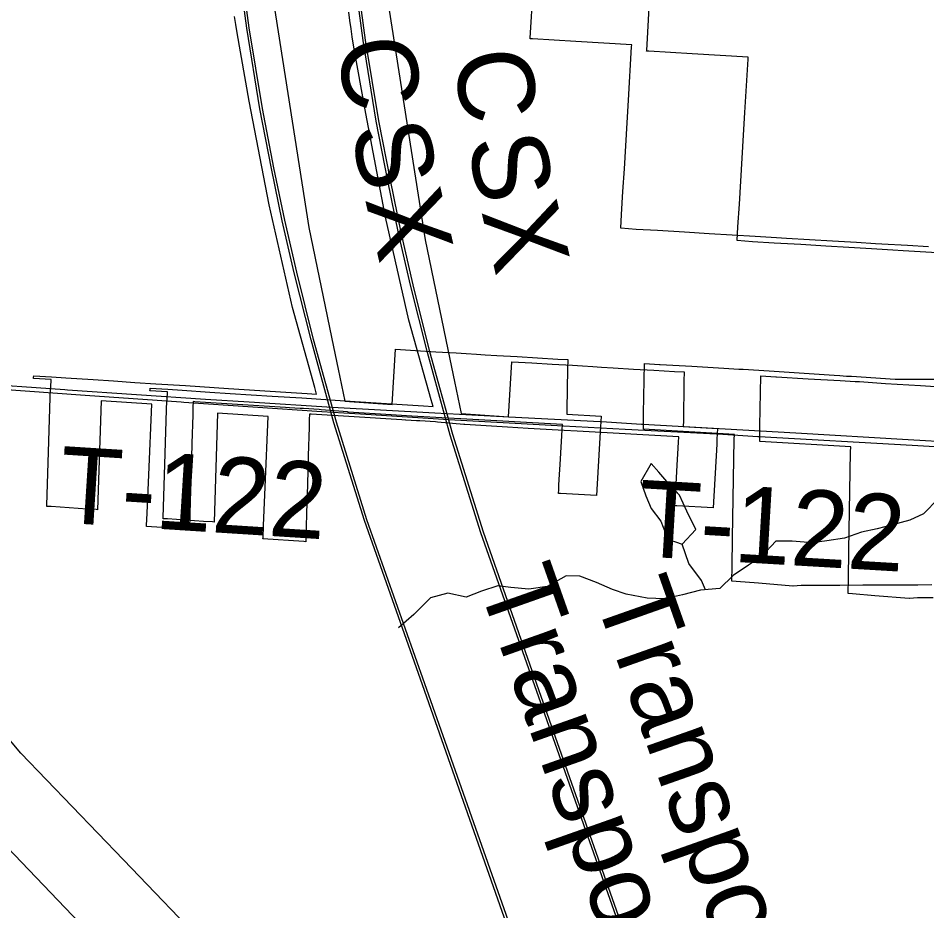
# Model space of a CAD drawing. Extents: x -38.2 to 41.9, y -4 to 24.9.
# Drawn here: x 6.275 to 6.95, y 18.764 to 19.427 of the extents above; entities that cross this region are included whole.
import ezdxf

# ---------------------------------------------------------------- set-up
doc = ezdxf.new("R2010")
doc.units = 0
for name, color, linetype in [('Default', 7, 'Continuous'), ('GM_X_City_Street', 7, 'Continuous'), ('GM_X_County_Road', 7, 'Continuous'), ('GM_X_Minor_Lake', 7, 'Continuous'), ('GM_X_Minor_River', 7, 'Continuous'), ('GM_X_Rail_Line', 7, 'Continuous'), ('GM_X_Rail_Line_Text', 7, 'Continuous'), ('GM_X_State_Location', 7, 'Continuous'), ('GM_X_Township_Road', 7, 'Continuous'), ('GM_X_Township_Road_Text', 7, 'Continuous')]:
    doc.layers.add(name, color=color, linetype=linetype)

msp = doc.modelspace()

# ---------------------------------------------------------------- linework, layer by layer
at = {"layer": 'Default'}
for points in [[(6.4559, 19.496), (6.49098, 19.27124), (6.50937, 19.18266), (6.51282, 19.16603), (6.51773, 19.14237), (6.55298, 19.1398), (6.55534, 19.18085), (6.57023, 19.17996), (6.58536, 19.17906), (6.60048, 19.17816), (6.60787, 19.17771), (6.61561, 19.17725), (6.62191, 19.17688), (6.63073, 19.17633), (6.64585, 19.1754), (6.66098, 19.17446), (6.6761, 19.17352), (6.68337, 19.17321), (6.68326, 19.16635), (6.68279, 19.13613), (6.68275, 19.13341), (6.68274, 19.13269), (6.70813, 19.13127), (6.70785, 19.12728), (6.70778, 19.12329), (6.70756, 19.11955), (6.70487, 19.0722), (6.67794, 19.07373), (6.67651, 19.07381), (6.67667, 19.07664), (6.67688, 19.08026), (6.67796, 19.09933), (6.67798, 19.09962), (6.6792, 19.12115), (6.67941, 19.12494), (6.60396, 19.12922), (6.59437, 19.12976), (6.56752, 19.13129), (6.55218, 19.13216), (6.52035, 19.13427), (6.51963, 19.13431), (6.50014, 19.13596), (6.49861, 19.13606), (6.48705, 19.13683), (6.48643, 19.13687), (6.48454, 19.13699), (6.47666, 19.13749), (6.47641, 19.13751), (6.47373, 19.13767), (6.43814, 19.13992), (6.40628, 19.14192), (6.40501, 19.142), (6.40489, 19.13798), (6.40472, 19.13231), (6.4041, 19.11091), (6.40347, 19.08961), (6.40285, 19.06832), (6.40224, 19.04762), (6.40222, 19.04712), (6.40095, 19.0472), (6.37048, 19.04918), (6.3705, 19.04991), (6.37079, 19.05925), (6.37205, 19.0877), (6.37438, 19.14014), (6.33664, 19.14266), (6.3341, 19.06172), (6.33307, 19.06179), (6.3264, 19.06224), (6.29948, 19.06405), (6.29637, 19.06417), (6.29639, 19.0649), (6.29785, 19.11275), (6.29885, 19.14519), (6.29892, 19.14709), (6.2993, 19.15276), (6.29966, 19.15844), (6.2865, 19.15929), (6.28654, 19.16001), (6.2866, 19.16118), (6.29978, 19.16033), (6.31041, 19.15964), (6.33089, 19.15832), (6.34598, 19.15734), (6.36167, 19.15633), (6.37736, 19.15531), (6.39934, 19.15389), (6.43122, 19.15183), (6.47396, 19.14907), (6.48986, 19.14804), (6.49681, 19.14759), (6.49545, 19.15243), (6.47884, 19.2118), (6.46147, 19.28819), (6.44678, 19.36513), (6.43774, 19.41587), (6.43681, 19.42202), (6.4359, 19.42817)], [(6.95154, 19.25696), (6.93589, 19.25787), (6.91687, 19.25898), (6.91211, 19.25926), (6.89801, 19.2601), (6.88011, 19.26118), (6.86306, 19.2622), (6.84602, 19.26323), (6.83844, 19.26368), (6.82271, 19.26463), (6.80564, 19.26566), (6.78857, 19.26668), (6.77015, 19.26779), (6.75017, 19.26899), (6.73414, 19.26995), (6.7228, 19.27093), (6.7234, 19.28094), (6.72442, 19.29796), (6.72544, 19.31497), (6.72645, 19.33199), (6.72747, 19.349), (6.72849, 19.36602), (6.73085, 19.40555), (6.73094, 19.40705), (6.68938, 19.40953), (6.67328, 19.4105), (6.65721, 19.41146), (6.65553, 19.41156), (6.65556, 19.41206), (6.65762, 19.44846)], [(6.95401, 19.00585), (6.94344, 19.00575), (6.93696, 19.00572), (6.93371, 19.00571), (6.92075, 19.00565), (6.91723, 19.00564), (6.90274, 19.00557), (6.88557, 19.00549), (6.87807, 19.00545), (6.86836, 19.0054), (6.85679, 19.00535), (6.85085, 19.00504), (6.85061, 19.00504), (6.82512, 19.00707), (6.80847, 19.00839), (6.80524, 19.00865), (6.80524, 19.00882), (6.80543, 19.01935), (6.80581, 19.04075), (6.80712, 19.1139), (6.80718, 19.11769), (6.73963, 19.12157), (6.73963, 19.12557), (6.73968, 19.1295), (6.73975, 19.13324), (6.74035, 19.17024), (6.75153, 19.1696), (6.75205, 19.16957), (6.77556, 19.16822), (6.79943, 19.16686), (6.81052, 19.16622), (6.81361, 19.16602), (6.833, 19.16476), (6.85908, 19.16307), (6.88129, 19.16162), (6.88543, 19.16136), (6.8905, 19.16103), (6.8942, 19.16079), (6.92671, 19.15867), (6.9422, 19.15865), (6.95656, 19.15863)]]:
    msp.add_lwpolyline(points, dxfattribs=at)
at = {"layer": 'GM_X_County_Road'}
for points in [[(6.54238, 19.48681), (6.57745, 19.26205), (6.59584, 19.17347), (6.5993, 19.15684), (6.60421, 19.13318), (6.63946, 19.13061), (6.64182, 19.17166), (6.65671, 19.17077), (6.67184, 19.16987), (6.68696, 19.16897), (6.69435, 19.16853), (6.70209, 19.16806), (6.70839, 19.16769), (6.71721, 19.16714), (6.73233, 19.16621), (6.74745, 19.16527), (6.76258, 19.16433), (6.76985, 19.16402), (6.76974, 19.15716), (6.76927, 19.12694), (6.76923, 19.12422), (6.76922, 19.1235), (6.79461, 19.12208), (6.79433, 19.11809), (6.79425, 19.1141), (6.79404, 19.11036), (6.79135, 19.06301), (6.76442, 19.06454), (6.76299, 19.06462), (6.76315, 19.06745), (6.76335, 19.07107), (6.76444, 19.09014), (6.76445, 19.09043), (6.76568, 19.11197), (6.76589, 19.11575), (6.69043, 19.12003), (6.68085, 19.12057), (6.654, 19.1221), (6.63865, 19.12297), (6.60683, 19.12508), (6.60611, 19.12512), (6.58662, 19.12677), (6.58508, 19.12688), (6.57353, 19.12765), (6.57291, 19.12768), (6.57102, 19.1278), (6.56314, 19.1283), (6.56288, 19.12832), (6.56021, 19.12849), (6.52462, 19.13073), (6.49275, 19.13273), (6.49148, 19.13281), (6.49137, 19.12879), (6.4912, 19.12312), (6.49057, 19.10172), (6.48995, 19.08042), (6.48932, 19.05913), (6.48872, 19.03843), (6.4887, 19.03793), (6.48742, 19.03801), (6.45696, 19.03999), (6.45698, 19.04072), (6.45726, 19.05006), (6.45853, 19.07851), (6.46085, 19.13095), (6.42312, 19.13347), (6.42058, 19.05253), (6.41954, 19.0526), (6.41288, 19.05305), (6.38596, 19.05486), (6.38284, 19.05498), (6.38287, 19.05571), (6.38433, 19.10356), (6.38533, 19.136), (6.38539, 19.1379), (6.38577, 19.14357), (6.38613, 19.14925), (6.37298, 19.1501), (6.37302, 19.15082), (6.37308, 19.15199), (6.38626, 19.15114), (6.39689, 19.15045), (6.41737, 19.14913), (6.43246, 19.14815), (6.44815, 19.14714), (6.46384, 19.14612), (6.48582, 19.1447), (6.51769, 19.14264), (6.56044, 19.13988), (6.57633, 19.13885), (6.58328, 19.1384), (6.58193, 19.14324), (6.56532, 19.20262), (6.54795, 19.279), (6.53326, 19.35594), (6.52422, 19.40668), (6.52329, 19.41283), (6.52238, 19.41898), (6.52148, 19.42513), (6.52062, 19.43123)], [(6.33156, 18.74361), (6.26678, 18.81099), (6.19068, 18.89012), (6.16568, 18.91927), (6.14879, 18.94351), (6.1397, 18.95874), (6.13142, 18.97442), (6.12397, 18.99051), (6.11949, 19.00145), (6.11538, 19.01254), (6.06671, 19.16827), (6.06312, 19.17932), (6.04638, 19.23325), (6.0322, 19.28484), (6.02363, 19.32547), (6.01909, 19.3528), (6.01409, 19.39407), (6.01194, 19.42186), (6.01053, 19.4664)], [(6.96659, 19.25199), (6.94954, 19.25302), (6.9325, 19.25404), (6.92492, 19.2545), (6.90918, 19.25544), (6.89212, 19.25647), (6.87505, 19.25749), (6.85663, 19.2586), (6.83665, 19.2598), (6.82062, 19.26076), (6.80928, 19.26174), (6.80988, 19.27176), (6.8109, 19.28877), (6.81191, 19.30578), (6.81293, 19.3228), (6.81395, 19.33981), (6.81497, 19.35683), (6.81733, 19.39636), (6.81742, 19.39786), (6.77585, 19.40034), (6.75976, 19.40131), (6.74369, 19.40227), (6.74201, 19.40237), (6.74204, 19.40287), (6.7441, 19.43927)], [(6.95483, 18.99621), (6.94327, 18.99616), (6.93733, 18.99585), (6.93708, 18.99585), (6.9116, 18.99788), (6.89494, 18.9992), (6.89172, 18.99946), (6.89172, 18.99963), (6.89191, 19.01016), (6.89229, 19.03156), (6.89359, 19.10471), (6.89366, 19.1085), (6.82611, 19.11238), (6.82611, 19.11638), (6.82615, 19.12031), (6.82622, 19.12405), (6.82683, 19.16105), (6.83801, 19.16041), (6.83853, 19.16038), (6.86203, 19.15903), (6.8859, 19.15767), (6.897, 19.15703), (6.90009, 19.15683), (6.91947, 19.15557), (6.94556, 19.15388), (6.96776, 19.15244)]]:
    msp.add_lwpolyline(points, dxfattribs=at)
at = {"layer": 'GM_X_Minor_Lake'}
for points in [[(6.75099, 19.08955), (6.74527, 19.09601), (6.7377, 19.08275), (6.74149, 19.07213), (6.74528, 19.06265), (6.75247, 19.05317), (6.75778, 19.0399), (6.76838, 19.03611)], [(6.76838, 19.03611), (6.77859, 19.0471), (6.77177, 19.06075), (6.76647, 19.0725), (6.757, 19.08274), (6.75099, 19.08955)]]:
    msp.add_lwpolyline(points, dxfattribs=at)
at = {"layer": 'GM_X_Minor_River'}
for points in [[(6.95873, 19.07015), (6.94776, 19.05878), (6.93754, 19.05385), (6.92468, 19.05045), (6.91332, 19.04742), (6.90159, 19.04515), (6.8891, 19.04061), (6.87586, 19.03872), (6.86488, 19.0372), (6.85012, 19.03835), (6.83801, 19.03835), (6.82742, 19.02698), (6.81758, 19.02054), (6.80623, 19.01297), (6.7964, 19.00311), (6.78201, 19.00198), (6.76877, 18.99858), (6.75515, 18.99555), (6.74228, 18.99593), (6.72676, 18.99897), (6.71654, 19.00239), (6.7048, 19.0077), (6.69231, 19.01226), (6.68209, 19.01264), (6.66809, 19.00469), (6.65447, 19.0028), (6.64122, 19.00394), (6.63138, 19.00508), (6.61927, 19.0013), (6.60792, 18.99675), (6.59429, 18.99979), (6.58143, 18.99638), (6.56894, 18.98388), (6.55759, 18.97402)], [(6.78566, 19.00227), (6.78277, 19.00918), (6.7733, 19.0217), (6.76838, 19.03611)]]:
    msp.add_lwpolyline(points, dxfattribs=at)
at = {"layer": 'GM_X_Rail_Line'}
for points in [[(6.82378, 18.22738), (6.69158, 18.60188), (6.65557, 18.70415), (6.57538, 18.93166), (6.53239, 19.05367), (6.50963, 19.1262), (6.49266, 19.18778), (6.48018, 19.23761), (6.47127, 19.27633), (6.46326, 19.31519), (6.45466, 19.3594), (6.44487, 19.41933), (6.43716, 19.47659)], [(6.82557, 18.22801), (6.69338, 18.60251), (6.65736, 18.70478), (6.57718, 18.93229), (6.5342, 19.05426), (6.51146, 19.12674), (6.4945, 19.18826), (6.48203, 19.23805), (6.47313, 19.27673), (6.46513, 19.31556), (6.45653, 19.35973), (6.44675, 19.41961), (6.43904, 19.47682)]]:
    msp.add_lwpolyline(points, dxfattribs=at)
at = {"layer": 'GM_X_Rail_Line_Text'}
for points in [[(6.91025, 18.21819), (6.77806, 18.5927), (6.74204, 18.69496), (6.66186, 18.92247), (6.61887, 19.04448), (6.59611, 19.11701), (6.57914, 19.17859), (6.56665, 19.22842), (6.55775, 19.26714), (6.54974, 19.306), (6.54114, 19.35021), (6.53135, 19.41014), (6.52363, 19.4674)], [(6.91205, 18.21882), (6.77985, 18.59332), (6.74384, 18.69559), (6.66366, 18.9231), (6.62067, 19.04508), (6.59794, 19.11755), (6.58098, 19.17907), (6.5685, 19.22886), (6.55961, 19.26754), (6.55161, 19.30637), (6.54301, 19.35054), (6.53323, 19.41042), (6.52552, 19.46763)]]:
    msp.add_lwpolyline(points, dxfattribs=at)
at = {"layer": 'GM_X_State_Location'}
msp.add_line((6.79499, 19.11806), (6.82464, 19.11619), dxfattribs=at)
for points in [[(6.13311, 19.16054), (6.15319, 19.15908), (6.32491, 19.14682), (6.39626, 19.14175)], [(6.39626, 19.14175), (6.39822, 19.14161), (6.50066, 19.13461), (6.53327, 19.13266), (6.59493, 19.12867), (6.671, 19.1246), (6.72616, 19.1215), (6.79401, 19.11812), (6.79499, 19.11806)], [(6.82464, 19.11619), (6.82563, 19.11613), (6.93937, 19.10974), (7.02288, 19.10473), (7.09154, 19.10063), (7.12633, 19.09907)]]:
    msp.add_lwpolyline(points, dxfattribs=at)
at = {"layer": 'GM_X_Township_Road'}
msp.add_line((6.70852, 19.12725), (6.73816, 19.12538), dxfattribs=at)
for points in [[(6.04663, 19.16973), (6.06671, 19.16827), (6.23843, 19.15601), (6.30979, 19.15094)], [(6.30979, 19.15094), (6.31174, 19.1508), (6.41418, 19.1438), (6.44679, 19.14185), (6.50845, 19.13786), (6.58452, 19.13379), (6.63968, 19.13069), (6.70753, 19.12731), (6.70852, 19.12725)], [(6.73816, 19.12538), (6.73915, 19.12532), (6.85289, 19.11893), (6.9364, 19.11392), (7.00506, 19.10982), (7.03985, 19.10826)]]:
    msp.add_lwpolyline(points, dxfattribs=at)
at = {"layer": 'GM_X_Township_Road_Text'}
msp.add_lwpolyline([(6.41804, 18.73442), (6.35326, 18.8018), (6.27716, 18.88093), (6.25216, 18.91008), (6.23527, 18.93432), (6.22618, 18.94955), (6.2179, 18.96523), (6.21045, 18.98132), (6.20597, 18.99226), (6.20186, 19.00335), (6.15319, 19.15908), (6.1496, 19.17013), (6.13286, 19.22406), (6.11868, 19.27565), (6.11011, 19.31628), (6.10557, 19.34361), (6.10056, 19.38488), (6.09841, 19.41267), (6.09701, 19.45721)], dxfattribs=at)

# ---------------------------------------------------------------- texts
at = {"layer": 'GM_X_City_Street'}
for s, height, rotation, p in [('C', 0.05663, 279.45893, (6.59769, 19.39968)), ('S', 0.05663, 281.58762, (6.60839, 19.33583)), ('X', 0.05663, 282.81859, (6.61914, 19.28348)), ('Transportation,', 0.0566288, 289.44483, (6.70263, 18.99841))]:
    msp.add_text(s, height=height, rotation=rotation, dxfattribs=at).set_placement(p)
at = {"layer": 'GM_X_Rail_Line_Text'}
for s, height, rotation, p in [('C', 0.05663, 279.45893, (6.51121, 19.40887)), ('S', 0.05663, 281.58762, (6.52191, 19.34502)), ('X', 0.05663, 282.81859, (6.53266, 19.29267)), ('Transportation,', 0.0566288, 289.44483, (6.61616, 19.0076))]:
    msp.add_text(s, height=height, rotation=rotation, dxfattribs=at).set_placement(p)
at = {"layer": 'GM_X_Township_Road_Text'}
for rotation, p in [(356.35599, (6.30429, 19.05232)), (356.63326, (6.73424, 19.02727))]:
    msp.add_text('T-122', height=0.056818, rotation=rotation, dxfattribs=at).set_placement(p)

doc.saveas('drawing.dxf')
